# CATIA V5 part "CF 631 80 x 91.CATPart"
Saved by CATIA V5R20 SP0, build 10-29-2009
Part number: CF 631 80 x 91
Definition: NONE
Nomenclature: CF 631 80 x 91
Source: Unknown
Description: CF 631 80 x 91
Bounding box of the stored display mesh (mm): x -13 to 78, y -55.5 to 55.5, z -55.5 to 55.5
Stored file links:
  C:\Users\Utente\Desktop\IO LAVORO\3D X SITO CF\X SITO\CF 631\CF 631 80 x 91.CATPart
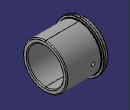
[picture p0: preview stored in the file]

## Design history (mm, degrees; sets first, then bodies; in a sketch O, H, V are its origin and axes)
Body1 "CF 631 80 x 91" (main body)
  Solid1: solid without history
